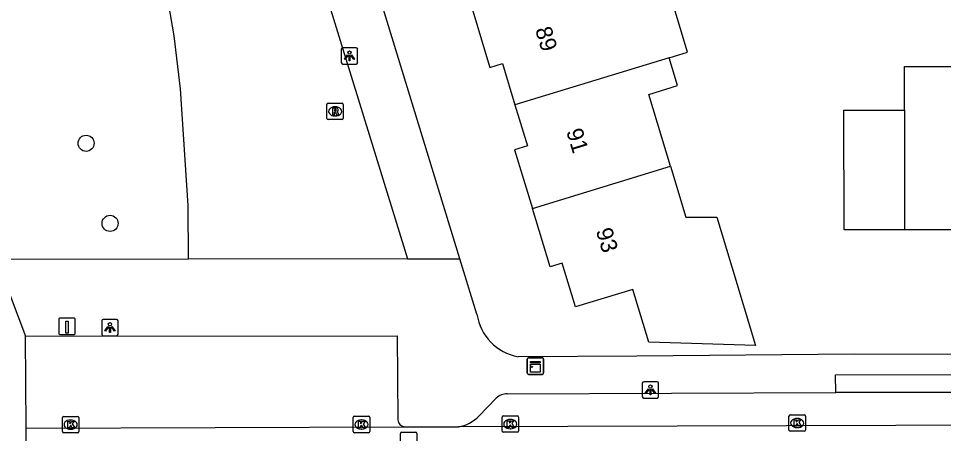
# Model space of a CAD drawing. Extents: x 160732 to 162105, y 387428 to 388479.
# Drawn here: x 161061 to 161117.3, y 388134.5 to 388159.8 of the extents above; entities that cross this region are included whole.
import ezdxf

# ---------------------------------------------------------------- set-up
doc = ezdxf.new("R2010")
doc.units = 0
for name, color, linetype in [('IMGEO_Boom', 7, 'Continuous'), ('IMGEO_Gemengd_bos', 7, 'Continuous'), ('IMGEO_Kast', 7, 'Continuous'), ('IMGEO_Kolk', 7, 'Continuous'), ('IMGEO_Laadpaal', 7, 'Continuous'), ('IMGEO_Lichtpunt', 7, 'Continuous'), ('IMGEO_Muur', 7, 'Continuous'), ('IMGEO_Pand', 7, 'Continuous'), ('IMGEO_Pand_nummerreeks', 7, 'Continuous'), ('IMGEO_Rijbaan_lokaal_open', 7, 'Continuous'), ('IMGEO_Rioolput', 7, 'Continuous'), ('IMGEO_Voetpad_open', 7, 'Continuous')]:
    doc.layers.add(name, color=color, linetype=linetype)

msp = doc.modelspace()

# ---------------------------------------------------------------- linework, layer by layer
at = {"layer": 'IMGEO_Boom'}
for centre in [(161065.108, 388152.179), (161066.565, 388147.308)]:
    msp.add_circle(centre, 0.489, dxfattribs=at)
at = {"layer": 'IMGEO_Gemengd_bos'}
msp.add_lwpolyline([(161071.335, 388145.12), (161071.321, 388148.398), (161070.857, 388155.485), (161070.474, 388158.722), (161069.066, 388166.872), (161067.15, 388174.79), (161067.28, 388177.001), (161067.581, 388177.765), (161064.844, 388182.109), (161062.475, 388180.764), (161059.198, 388177.928), (161025.961, 388178.316), (161025.178, 388178.337), (161024.512, 388178.664), (161024.244, 388178.924), (161023.958, 388179.404), (161023.832, 388180.135), (161023.583, 388190.665), (161018.116, 388220.822)], dxfattribs=at)
at = {"layer": 'IMGEO_Kast'}
for p, q in [((161091.961, 388138.194), (161091.961, 388139.035)), ((161091.961, 388139.035), (161091.961, 388138.194)), ((161092.036, 388139.119), (161092.877, 388139.119)), ((161092.877, 388139.119), (161092.036, 388139.119)), ((161092.961, 388139.044), (161092.961, 388138.203)), ((161092.961, 388138.203), (161092.961, 388139.044)), ((161092.886, 388138.119), (161092.045, 388138.119)), ((161092.045, 388138.119), (161092.886, 388138.119))]:
    msp.add_line(p, q, dxfattribs=at)
for points in [[(161092.156, 388138.909), (161092.756, 388138.909), (161092.756, 388138.824), (161092.156, 388138.824), (161092.156, 388138.909)], [(161092.156, 388138.734), (161092.756, 388138.734), (161092.756, 388138.245), (161092.156, 388138.245), (161092.156, 388138.734)]]:
    msp.add_lwpolyline(points, dxfattribs=at)
msp.add_circle((161092.24, 388138.583), 0.0377, dxfattribs=at)
for centre, start, end in [((161092.039, 388139.041), 92.4484, 184.2845), ((161092.039, 388139.041), 92.4484, 184.2845), ((161092.883, 388139.041), 2.4484, 94.2845), ((161092.883, 388139.041), 2.4484, 94.2845), ((161092.039, 388138.197), 182.4484, 274.2845), ((161092.039, 388138.197), 182.4484, 274.2845), ((161092.883, 388138.197), 272.4484, 4.2845), ((161092.883, 388138.197), 272.4484, 4.2845)]:
    msp.add_arc(centre, 0.0779, start, end, dxfattribs=at)
at = {"layer": 'IMGEO_Kolk'}
for p, q in [((161063.666, 388134.631), (161063.666, 388135.483)), ((161063.741, 388135.557), (161064.593, 388135.557)), ((161064.154, 388135.337), (161064.179, 388135.337)), ((161064.667, 388135.483), (161064.667, 388134.631)), ((161081.371, 388134.642), (161081.371, 388135.494)), ((161081.446, 388135.568), (161082.298, 388135.568)), ((161081.859, 388135.348), (161081.884, 388135.348)), ((161082.372, 388135.494), (161082.372, 388134.642)), ((161090.428, 388134.666), (161090.428, 388135.518)), ((161090.503, 388135.592), (161091.355, 388135.592)), ((161090.916, 388135.372), (161090.941, 388135.372)), ((161091.429, 388135.518), (161091.429, 388134.666)), ((161107.894, 388134.73), (161107.894, 388135.582)), ((161107.969, 388135.656), (161108.821, 388135.656)), ((161108.382, 388135.436), (161108.407, 388135.436)), ((161108.895, 388135.582), (161108.895, 388134.73)), ((161064.177, 388134.777), (161064.152, 388134.777)), ((161081.882, 388134.788), (161081.857, 388134.788)), ((161090.939, 388134.812), (161090.914, 388134.812)), ((161108.821, 388134.656), (161107.969, 388134.656)), ((161108.405, 388134.876), (161108.38, 388134.876)), ((161064.593, 388134.557), (161063.741, 388134.557)), ((161082.298, 388134.568), (161081.446, 388134.568)), ((161091.355, 388134.592), (161090.503, 388134.592))]:
    msp.add_line(p, q, dxfattribs=at)
for points in [[(161063.666, 388134.631), (161063.666, 388135.483)], [(161063.741, 388135.557), (161064.593, 388135.557)], [(161063.987, 388135.257), (161064.11, 388135.257), (161064.11, 388135.106), (161064.24, 388135.257), (161064.404, 388135.257), (161064.258, 388135.106), (161064.411, 388134.857), (161064.259, 388134.857), (161064.174, 388135.021), (161064.11, 388134.954), (161064.11, 388134.857), (161063.987, 388134.857), (161063.987, 388135.257)], [(161064.667, 388135.483), (161064.667, 388134.631)], [(161081.371, 388134.642), (161081.371, 388135.494)], [(161081.446, 388135.568), (161082.298, 388135.568)], [(161081.692, 388135.268), (161081.815, 388135.268), (161081.815, 388135.117), (161081.945, 388135.268), (161082.109, 388135.268), (161081.963, 388135.117), (161082.116, 388134.868), (161081.964, 388134.868), (161081.879, 388135.032), (161081.815, 388134.965), (161081.815, 388134.868), (161081.692, 388134.868), (161081.692, 388135.268)], [(161082.372, 388135.494), (161082.372, 388134.642)], [(161090.428, 388134.666), (161090.428, 388135.518)], [(161090.503, 388135.592), (161091.355, 388135.592)], [(161090.749, 388135.292), (161090.872, 388135.292), (161090.872, 388135.141), (161091.002, 388135.292), (161091.166, 388135.292), (161091.02, 388135.141), (161091.173, 388134.892), (161091.021, 388134.892), (161090.936, 388135.056), (161090.872, 388134.989), (161090.872, 388134.892), (161090.749, 388134.892), (161090.749, 388135.292)], [(161091.429, 388135.518), (161091.429, 388134.666)], [(161107.894, 388134.73), (161107.894, 388135.582)], [(161107.969, 388135.656), (161108.821, 388135.656)], [(161108.215, 388135.356), (161108.338, 388135.356), (161108.338, 388135.205), (161108.468, 388135.356), (161108.632, 388135.356), (161108.486, 388135.205), (161108.639, 388134.956), (161108.487, 388134.956), (161108.402, 388135.12), (161108.338, 388135.053), (161108.338, 388134.956), (161108.215, 388134.956), (161108.215, 388135.356)], [(161108.895, 388135.582), (161108.895, 388134.73)], [(161108.821, 388134.656), (161107.969, 388134.656)], [(161064.593, 388134.557), (161063.741, 388134.557)], [(161082.298, 388134.568), (161081.446, 388134.568)], [(161091.355, 388134.592), (161090.503, 388134.592)]]:
    msp.add_lwpolyline(points, dxfattribs=at)
for centre, start, end in [((161063.743, 388135.481), 91.552, 178.448), ((161063.743, 388135.481), 91.552, 178.448), ((161064.591, 388135.481), 1.552, 88.448), ((161064.591, 388135.481), 1.552, 88.448), ((161081.448, 388135.492), 91.552, 178.448), ((161081.448, 388135.492), 91.552, 178.448), ((161082.296, 388135.492), 1.552, 88.448), ((161082.296, 388135.492), 1.552, 88.448), ((161090.505, 388135.516), 91.552, 178.448), ((161090.505, 388135.516), 91.552, 178.448), ((161091.353, 388135.516), 1.552, 88.448), ((161091.353, 388135.516), 1.552, 88.448), ((161107.971, 388135.58), 91.552, 178.448), ((161107.971, 388135.58), 91.552, 178.448), ((161108.819, 388135.58), 1.552, 88.448), ((161108.819, 388135.58), 1.552, 88.448), ((161063.743, 388134.633), 181.552, 268.448), ((161063.743, 388134.633), 181.552, 268.448), ((161064.591, 388134.633), 271.552, 358.448), ((161064.591, 388134.633), 271.552, 358.448), ((161081.448, 388134.644), 181.552, 268.448), ((161081.448, 388134.644), 181.552, 268.448), ((161082.296, 388134.644), 271.552, 358.448), ((161082.296, 388134.644), 271.552, 358.448), ((161090.505, 388134.668), 181.552, 268.448), ((161090.505, 388134.668), 181.552, 268.448), ((161091.353, 388134.668), 271.552, 358.448), ((161091.353, 388134.668), 271.552, 358.448), ((161107.971, 388134.732), 181.552, 268.448), ((161107.971, 388134.732), 181.552, 268.448), ((161108.819, 388134.732), 271.552, 358.448), ((161108.819, 388134.732), 271.552, 358.448)]:
    msp.add_arc(centre, 0.0765, start, end, dxfattribs=at)
for centre, major_axis, ratio, start_param, end_param in [((161064.153, 388135.057), (-0.387, 0.002), 0.722429, 4.712389, 7.853982), ((161064.178, 388135.057), (-0.39, 0.002), 0.717154, 1.570796, 4.712389), ((161081.858, 388135.068), (-0.387, 0.002), 0.722429, 4.712389, 7.853982), ((161081.883, 388135.068), (-0.39, 0.002), 0.717154, 1.570796, 4.712389), ((161090.915, 388135.092), (-0.387, 0.002), 0.722429, 4.712389, 7.853982), ((161090.94, 388135.092), (-0.39, 0.002), 0.717154, 1.570796, 4.712389), ((161108.381, 388135.156), (-0.387, 0.002), 0.722429, 4.712389, 7.853982), ((161108.406, 388135.156), (-0.39, 0.002), 0.717154, 1.570796, 4.712389)]:
    msp.add_ellipse(centre, major_axis=major_axis, ratio=ratio, start_param=start_param, end_param=end_param, dxfattribs=at)
at = {"layer": 'IMGEO_Laadpaal'}
for p, q in [((161063.448, 388141.459), (161063.448, 388140.618)), ((161063.448, 388141.459), (161063.448, 388140.618)), ((161064.364, 388141.543), (161063.523, 388141.543)), ((161064.364, 388141.543), (161063.523, 388141.543)), ((161064.448, 388140.627), (161064.448, 388141.468)), ((161064.448, 388140.627), (161064.448, 388141.468)), ((161063.532, 388140.543), (161064.373, 388140.543)), ((161063.532, 388140.543), (161064.373, 388140.543))]:
    msp.add_line(p, q, dxfattribs=at)
msp.add_lwpolyline([(161063.863, 388141.356), (161064.023, 388141.356), (161064.023, 388140.623), (161063.863, 388140.623), (161063.863, 388141.356)], dxfattribs=at)
for centre, start, end in [((161063.526, 388141.465), 92.4484, 184.2845), ((161063.526, 388141.465), 92.4484, 184.2845), ((161064.37, 388141.465), 2.4484, 94.2845), ((161064.37, 388141.465), 2.4484, 94.2845), ((161063.526, 388140.621), 182.4484, 274.2845), ((161063.526, 388140.621), 182.4484, 274.2845), ((161064.37, 388140.621), 272.4484, 4.2845), ((161064.37, 388140.621), 272.4484, 4.2845)]:
    msp.add_arc(centre, 0.0779, start, end, dxfattribs=at)
at = {"layer": 'IMGEO_Lichtpunt'}
for p, q in [((161080.642, 388157.903), (161080.642, 388157.096)), ((161080.642, 388157.903), (161080.642, 388157.096)), ((161081.544, 388157.998), (161080.736, 388157.998)), ((161081.544, 388157.998), (161080.736, 388157.998)), ((161081.638, 388157.096), (161081.638, 388157.903)), ((161081.638, 388157.096), (161081.638, 388157.903)), ((161080.736, 388157.002), (161081.544, 388157.002)), ((161080.736, 388157.002), (161081.544, 388157.002)), ((161066.961, 388141.464), (161066.153, 388141.464)), ((161066.961, 388141.464), (161066.153, 388141.464)), ((161066.059, 388141.369), (161066.059, 388140.562)), ((161066.059, 388141.369), (161066.059, 388140.562)), ((161067.055, 388140.562), (161067.055, 388141.369)), ((161067.055, 388140.562), (161067.055, 388141.369)), ((161066.153, 388140.468), (161066.961, 388140.468)), ((161066.153, 388140.468), (161066.961, 388140.468)), ((161098.963, 388137.575), (161098.963, 388136.768)), ((161098.963, 388137.575), (161098.963, 388136.768)), ((161099.865, 388137.67), (161099.057, 388137.67)), ((161099.865, 388137.67), (161099.057, 388137.67)), ((161099.959, 388136.768), (161099.959, 388137.575)), ((161099.959, 388136.768), (161099.959, 388137.575)), ((161099.057, 388136.674), (161099.865, 388136.674)), ((161099.057, 388136.674), (161099.865, 388136.674))]:
    msp.add_line(p, q, dxfattribs=at)
for points in [[(161081.016, 388157.567), (161081.055, 388157.539), (161080.867, 388157.277), (161080.829, 388157.304), (161081.016, 388157.567)], [(161081.118, 388157.519), (161081.165, 388157.519), (161081.165, 388157.197), (161081.118, 388157.197), (161081.118, 388157.519)], [(161081.228, 388157.539), (161081.266, 388157.566), (161081.453, 388157.304), (161081.414, 388157.276), (161081.228, 388157.539)], [(161066.433, 388141.033), (161066.472, 388141.005), (161066.284, 388140.743), (161066.246, 388140.77), (161066.433, 388141.033)], [(161066.535, 388140.985), (161066.582, 388140.985), (161066.582, 388140.663), (161066.535, 388140.663), (161066.535, 388140.985)], [(161066.645, 388141.005), (161066.683, 388141.032), (161066.87, 388140.77), (161066.831, 388140.742), (161066.645, 388141.005)], [(161099.337, 388137.239), (161099.376, 388137.211), (161099.188, 388136.949), (161099.15, 388136.976), (161099.337, 388137.239)], [(161099.439, 388137.191), (161099.486, 388137.191), (161099.486, 388136.869), (161099.439, 388136.869), (161099.439, 388137.191)], [(161099.549, 388137.211), (161099.587, 388137.238), (161099.774, 388136.976), (161099.735, 388136.948), (161099.549, 388137.211)]]:
    msp.add_lwpolyline(points, dxfattribs=at)
for centre in [(161081.141, 388157.701), (161066.558, 388141.167), (161099.462, 388137.373)]:
    msp.add_circle(centre, 0.0994, dxfattribs=at)
for centre, start, end in [((161080.736, 388157.903), 90, 180), ((161080.736, 388157.903), 90, 180), ((161081.544, 388157.903), 0, 90), ((161081.544, 388157.903), 0, 90), ((161080.736, 388157.096), 180, 270), ((161080.736, 388157.096), 180, 270), ((161081.544, 388157.096), 270, 0), ((161081.544, 388157.096), 270, 360), ((161066.153, 388141.369), 90, 180), ((161066.153, 388141.369), 90, 180), ((161066.961, 388141.369), 0, 90), ((161066.961, 388141.369), 0, 90), ((161066.153, 388140.562), 180, 270), ((161066.153, 388140.562), 180, 270), ((161066.961, 388140.562), 270, 0), ((161066.961, 388140.562), 270, 360), ((161099.057, 388137.575), 90, 180), ((161099.057, 388137.575), 90, 180), ((161099.865, 388137.575), 0, 90), ((161099.865, 388137.575), 0, 90), ((161099.057, 388136.768), 180, 270), ((161099.057, 388136.768), 180, 270), ((161099.865, 388136.768), 270, 0), ((161099.865, 388136.768), 270, 360)]:
    msp.add_arc(centre, 0.0946, start, end, dxfattribs=at)
at = {"layer": 'IMGEO_Muur'}
msp.add_lwpolyline([(161111.891, 388139.34), (161098.635, 388139.224)], dxfattribs=at)
at = {"layer": 'IMGEO_Pand'}
for points in [[(161100.598, 388157.387), (161101.709, 388157.724), (161099.904, 388163.746)], [(161088.622, 388160.312), (161089.689, 388156.799), (161090.446, 388157.029), (161091.207, 388154.525)], [(161100.598, 388157.387), (161091.207, 388154.525)], [(161100.682, 388150.782), (161099.353, 388155.158), (161101.112, 388155.692), (161100.598, 388157.387)], [(161114.922, 388154.204), (161114.927, 388156.851), (161119.327, 388156.851), (161119.327, 388154.851), (161125.122, 388154.851), (161125.111, 388153.956), (161125.113, 388152.259)], [(161091.207, 388154.525), (161091.967, 388152.022), (161091.189, 388151.786), (161092.272, 388148.22)], [(161114.927, 388146.921), (161111.249, 388146.918), (161111.243, 388154.201), (161114.922, 388154.204)], [(161114.922, 388154.204), (161114.927, 388146.921)], [(161100.682, 388150.782), (161101.623, 388147.682), (161103.498, 388147.681), (161104.412, 388144.666), (161105.863, 388139.881), (161099.367, 388140.087), (161098.393, 388143.292), (161094.9, 388142.231), (161094.096, 388144.88), (161093.355, 388144.655), (161092.272, 388148.22)], [(161092.272, 388148.22), (161100.682, 388150.782)], [(161125.122, 388144.259), (161118.554, 388144.254), (161118.552, 388146.923), (161114.927, 388146.921)]]:
    msp.add_lwpolyline(points, dxfattribs=at)
at = {"layer": 'IMGEO_Rijbaan_lokaal_open'}
for points in [[(161061.45, 388134.853), (161084.468, 388134.923)], [(161061.56, 388100.662), (161061.45, 388134.853)], [(161084.468, 388134.923), (161087.767, 388134.917)], [(161147.688, 388135.104), (161087.767, 388134.917)]]:
    msp.add_lwpolyline(points, dxfattribs=at)
at = {"layer": 'IMGEO_Rioolput'}
for p, q in [((161079.763, 388153.696), (161079.763, 388154.548)), ((161079.838, 388154.622), (161080.69, 388154.622)), ((161080.251, 388154.402), (161080.276, 388154.402)), ((161080.764, 388154.548), (161080.764, 388153.696)), ((161080.274, 388153.842), (161080.249, 388153.842)), ((161080.69, 388153.622), (161079.838, 388153.622)), ((161084.24, 388133.667), (161084.24, 388134.519)), ((161084.315, 388134.593), (161085.167, 388134.593)), ((161085.241, 388134.519), (161085.241, 388133.667))]:
    msp.add_line(p, q, dxfattribs=at)
for points in [[(161079.763, 388153.696), (161079.763, 388154.548)], [(161079.838, 388154.622), (161080.69, 388154.622)], [(161080.764, 388154.548), (161080.764, 388153.696)], [(161080.352, 388154.32), (161080.1, 388154.322), (161080.1, 388153.922)], [(161080.1, 388153.922), (161080.224, 388153.922), (161080.224, 388154.084), (161080.235, 388154.084)], [(161080.278, 388154.241), (161080.224, 388154.241), (161080.224, 388154.16)], [(161080.224, 388154.16), (161080.276, 388154.16)], [(161080.282, 388154.055), (161080.353, 388153.922), (161080.493, 388153.922), (161080.428, 388154.048)], [(161080.69, 388153.622), (161079.838, 388153.622)], [(161084.24, 388133.667), (161084.24, 388134.519)], [(161084.315, 388134.593), (161085.167, 388134.593)], [(161085.241, 388134.519), (161085.241, 388133.667)]]:
    msp.add_lwpolyline(points, dxfattribs=at)
for centre, radius, start, end in [((161079.84, 388154.546), 0.0765, 91.552, 178.448), ((161079.84, 388154.546), 0.0765, 91.552, 178.448), ((161080.688, 388154.546), 0.0765, 1.552, 88.448), ((161080.688, 388154.546), 0.0765, 1.552, 88.448), ((161080.234, 388154.031), 0.0533, 26.0293, 88.6989), ((161080.26, 388154.349), 0.19, 274.7715, 282.9687), ((161080.284, 388154.145), 0.0964, 77.0061, 93.1865), ((161080.298, 388154.202), 0.0378, 276.6634, 79.6772), ((161080.351, 388154.21), 0.109, 350.3612, 89.416), ((161080.349, 388154.21), 0.112, 277.5842, 350.9817), ((161080.333, 388153.995), 0.108, 29.5134, 73.7905), ((161079.84, 388153.698), 0.0765, 181.552, 268.448), ((161079.84, 388153.698), 0.0765, 181.552, 268.448), ((161080.688, 388153.698), 0.0765, 271.552, 358.448), ((161080.688, 388153.698), 0.0765, 271.552, 358.448), ((161084.317, 388134.517), 0.0765, 91.552, 178.448), ((161084.317, 388134.517), 0.0765, 91.552, 178.448), ((161085.165, 388134.517), 0.0765, 1.552, 88.448), ((161085.165, 388134.517), 0.0765, 1.552, 88.448)]:
    msp.add_arc(centre, radius, start, end, dxfattribs=at)
for centre, major_axis, ratio, start_param, end_param in [((161080.25, 388154.122), (-0.387, 0.002), 0.722429, 4.712389, 7.853982), ((161080.275, 388154.122), (-0.39, 0.002), 0.717154, 1.570796, 4.712389)]:
    msp.add_ellipse(centre, major_axis=major_axis, ratio=ratio, start_param=start_param, end_param=end_param, dxfattribs=at)
at = {"layer": 'IMGEO_Voetpad_open'}
for points in [[(161087.866, 388145.147), (161071.684, 388197.975)], [(161070.539, 388190.947), (161084.681, 388145.142)], [(161071.335, 388145.12), (161060.488, 388145.102)], [(161084.681, 388145.142), (161071.335, 388145.12)], [(161084.681, 388145.142), (161087.866, 388145.147)], [(161088.898, 388141.778), (161087.866, 388145.147)], [(161060.489, 388142.917), (161061.422, 388140.438)], [(161061.422, 388140.438), (161084.044, 388140.461), (161084.081, 388135.347)], [(161061.45, 388134.853), (161061.422, 388140.438)], [(161151.971, 388139.278), (161111.891, 388139.34), (161098.635, 388139.224), (161091.402, 388139.194)], [(161110.754, 388137.021), (161110.72, 388138.081), (161119.766, 388138.111), (161119.782, 388137.014)], [(161090.746, 388136.938), (161110.754, 388137.021)], [(161119.782, 388137.014), (161110.754, 388137.021)], [(161089.023, 388135.578), (161090.075, 388136.668)]]:
    msp.add_lwpolyline(points, dxfattribs=at)
for centre, radius, start, end in [((161091.976, 388142.255), 3.115, 188.8174, 259.381), ((161090.764, 388135.924), 1.014, 91.0301, 132.808), ((161084.562, 388135.397), 0.483, 185.9491, 258.8265), ((161087.332, 388137.267), 2.39, 280.4823, 315.0311)]:
    msp.add_arc(centre, radius, start, end, dxfattribs=at)

# ---------------------------------------------------------------- texts
at = {"layer": 'IMGEO_Pand_nummerreeks'}
for s, rotation, p in [('89', 286.9929, (161092.43, 388159.11)), ('91', 286.9929, (161094.323, 388152.918)), ('93', 286.8836, (161096.128, 388146.862))]:
    msp.add_text(s, height=1, rotation=rotation, dxfattribs=at).set_placement(p)

doc.saveas('drawing.dxf')
